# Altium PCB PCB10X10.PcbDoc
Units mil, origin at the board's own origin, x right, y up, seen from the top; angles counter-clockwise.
Board outline 3937.01 x 3937.01 mil, 2 copper layers (Top Layer, Bottom Layer); 55 components, 39 nets, 181 pads, 21 vias.
Unrouted connection lines stored in the file: 1.
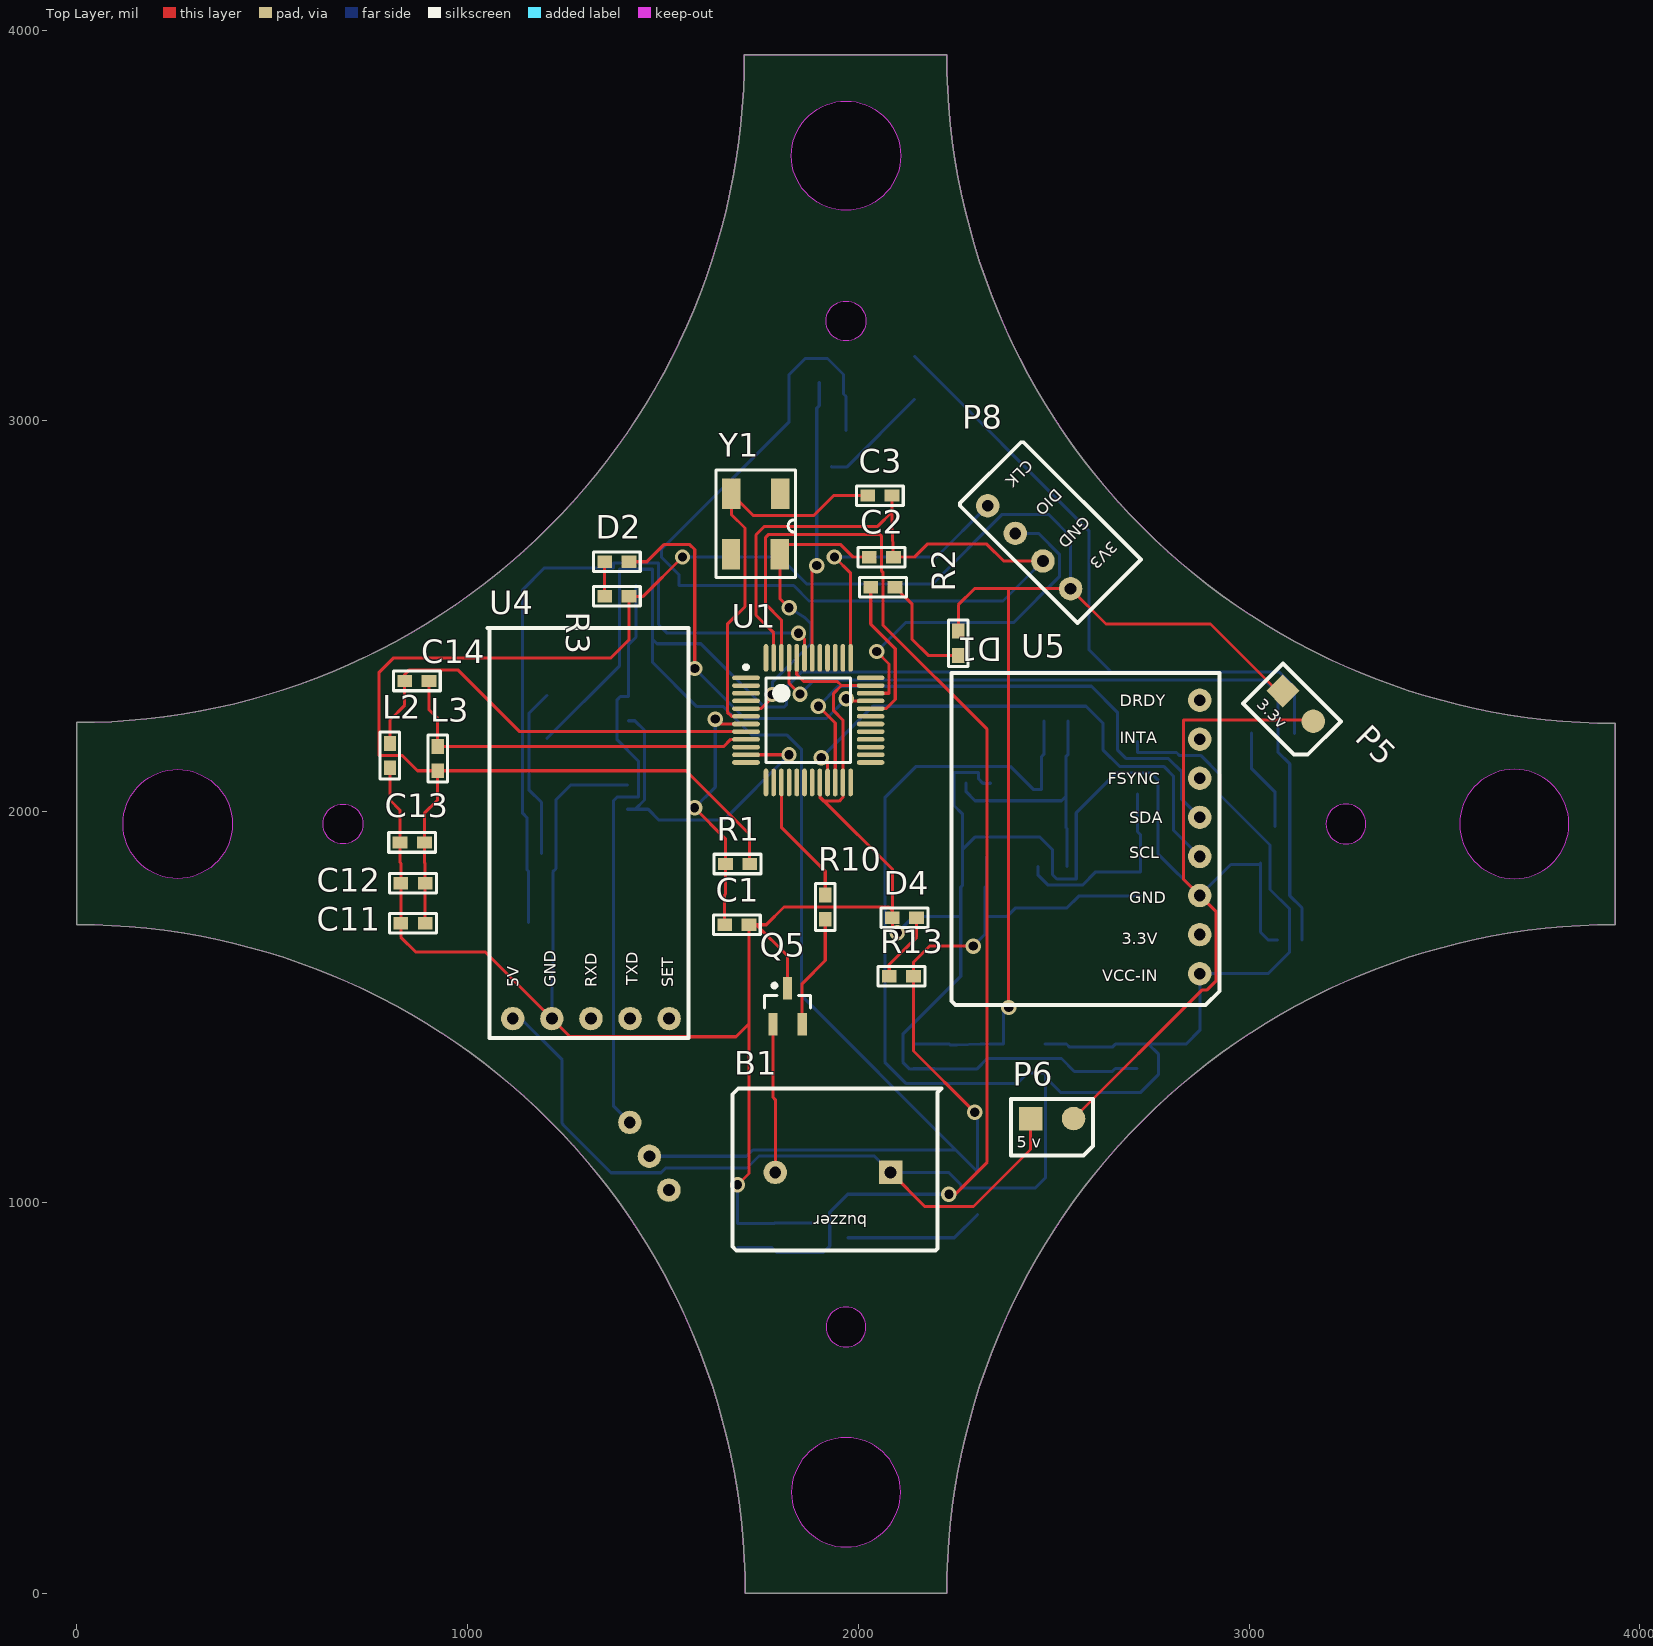
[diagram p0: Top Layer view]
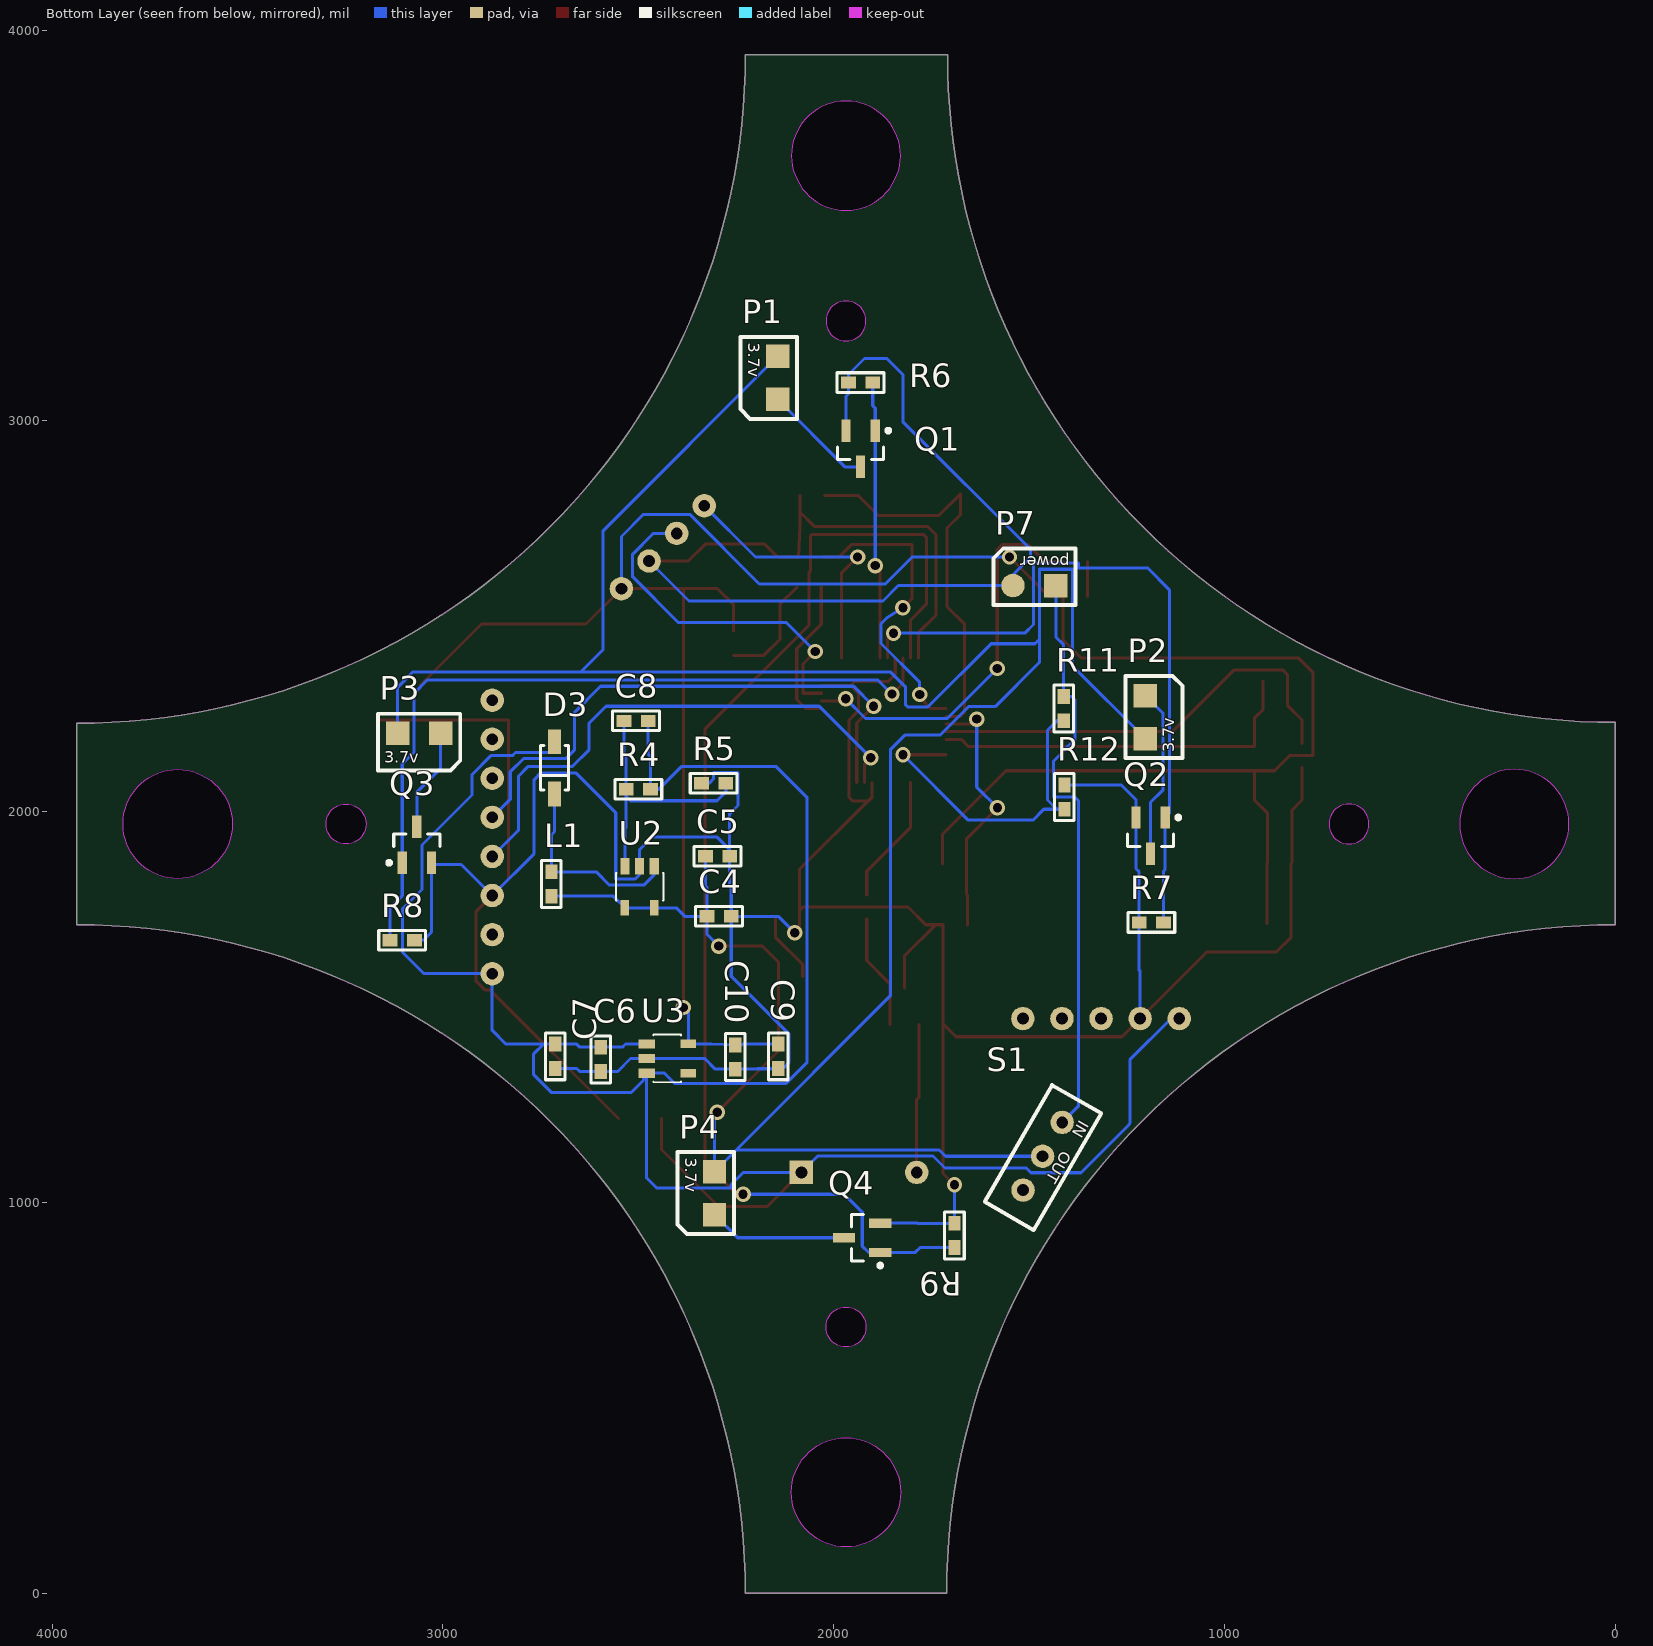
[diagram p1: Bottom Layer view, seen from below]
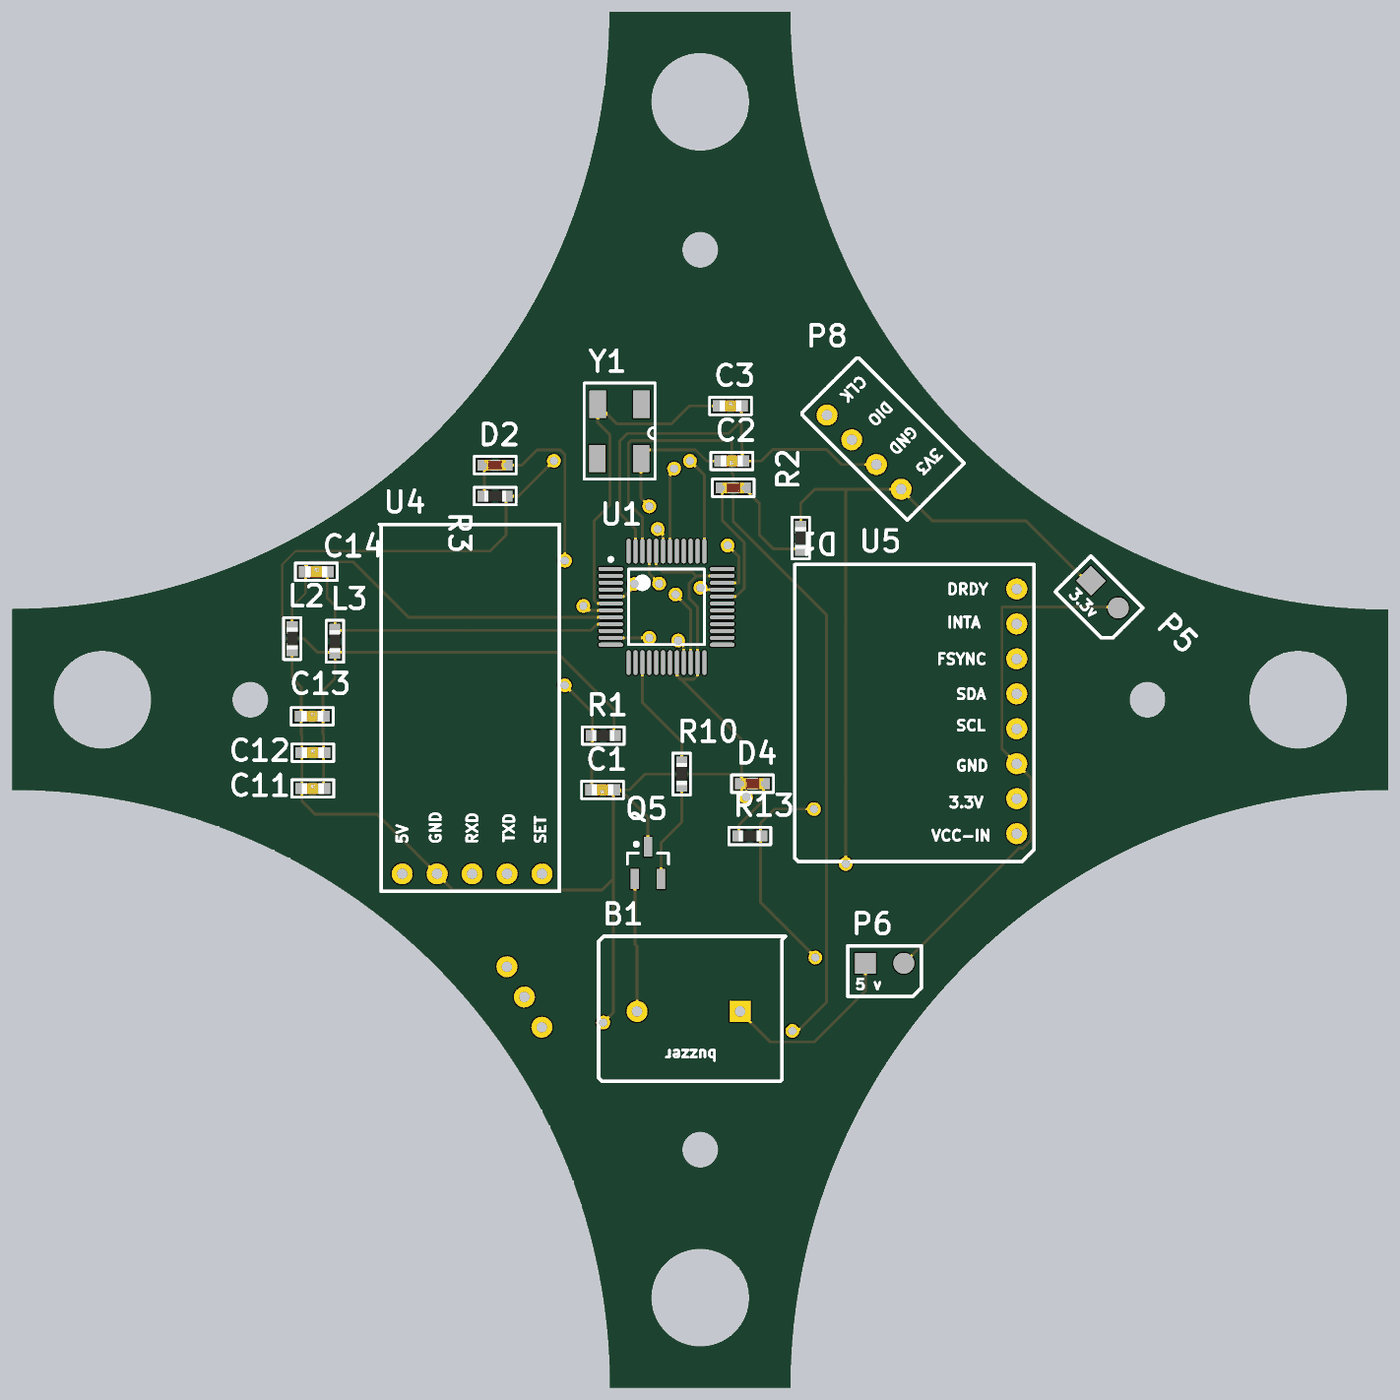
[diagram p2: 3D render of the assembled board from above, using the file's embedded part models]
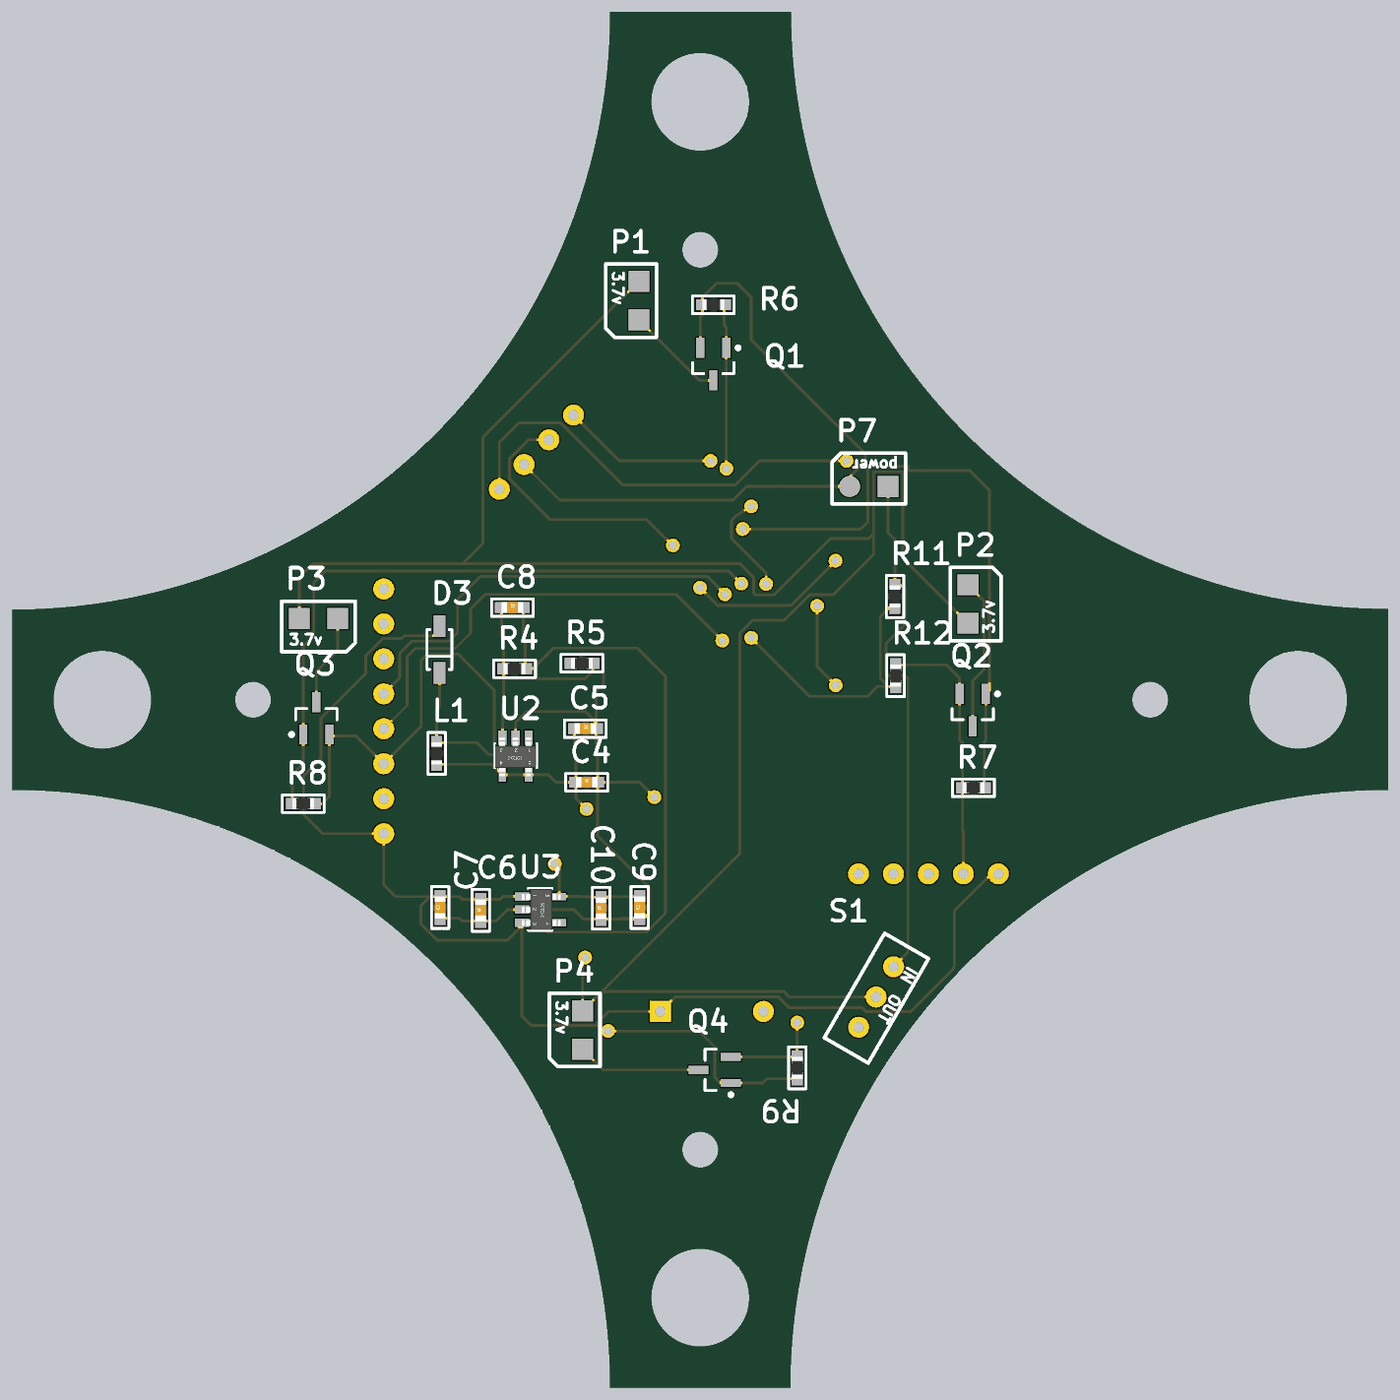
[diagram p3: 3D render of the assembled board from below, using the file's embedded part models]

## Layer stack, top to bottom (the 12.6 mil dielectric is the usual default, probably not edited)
Top Solder: solder mask 0.4, Solder Resist, Dk 3.5
Top Layer: signal copper 1.4
Dielectric 1: dielectric 12.6, FR-4, Dk 4.8
Bottom Layer: signal copper 1.4
Bottom Solder: solder mask 0.4, Solder Resist, Dk 3.5

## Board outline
0,1710.63 0,2228.33 ccw(c0,3937.01) 1708.68,3937.01 2226.38,3937.01 ccw(c3937.01,3937.01) 3937.01,2226.38 3937.01,1710.63 ccw(c3937.01,0) 2226.38,0 1710.63,0 ccw(c0,0)
cut-out: 1968.5,3539.36 cw(c1968.5,3679.13) 1828.73,3679.13 cw(c1968.5,3679.13) 1968.5,3818.91 cw(c1968.5,3679.13) 2108.28,3679.13 cw(c1968.5,3679.13)
cut-out: 3539.36,1968.5 ccw(c3679.13,1968.5) 3679.13,1828.73 ccw(c3679.13,1968.5) 3818.91,1968.5 ccw(c3679.13,1968.5) 3679.13,2108.28 ccw(c3679.13,1968.5)
cut-out: 1828.73,257.87 ccw(c1968.5,257.87) 1968.5,118.1 ccw(c1968.5,257.87) 2108.28,257.87 ccw(c1968.5,257.87) 1968.5,397.65 ccw(c1968.5,257.87)
cut-out: 257.87,1828.73 cw(c257.87,1968.5) 118.1,1968.5 cw(c257.87,1968.5) 257.87,2108.28 cw(c257.87,1968.5) 397.65,1968.5 cw(c257.87,1968.5)
cut-out: 681.1,1917.32 cw(c681.1,1968.5) 629.92,1968.5 cw(c681.1,1968.5) 681.1,2019.68 cw(c681.1,1968.5) 732.28,1968.5 cw(c681.1,1968.5)
cut-out: 3196.85,1968.5 ccw(c3248.03,1968.5) 3248.03,1917.32 ccw(c3248.03,1968.5) 3299.21,1968.5 ccw(c3248.03,1968.5) 3248.03,2019.68 ccw(c3248.03,1968.5)
cut-out: 1917.32,681.1 ccw(c1968.5,681.1) 1968.5,629.92 ccw(c1968.5,681.1) 2019.68,681.1 ccw(c1968.5,681.1) 1968.5,732.28 ccw(c1968.5,681.1)
cut-out: 1968.5,3204.72 cw(c1968.5,3255.91) 1917.32,3255.91 cw(c1968.5,3255.91) 1968.5,3307.09 cw(c1968.5,3255.91) 2019.68,3255.91 cw(c1968.5,3255.91)

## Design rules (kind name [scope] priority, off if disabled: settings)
Clearance [All] p1: gap=7.87
DiffPairsRouting [All] p1: maxlimit=7.87 minlimit=7.87 mostfreqgap=7.87 toplayer_minwidth=15 toplayer_maxwidth=15 toplayer_prefwidth=15 bottomlayer_minwidth=15 bottomlayer_maxwidth=15 bottomlayer_prefwidth=15 maxuncoupledlength=500
PolygonConnect [All] p1: connectstyle=Relief reliefconductorwidth=10 reliefentries=4 polygonreliefangle="90 Angle" airgapwidth=10
RoutingCorners [All] p1: cornerstyle=45-Degree minsetback=78.74 maxsetback=78.74
RoutingVias [All] p1: holewidth=23.62 width=39.37 viastyle="Through Hole" minholewidth=28 minwidth=50 maxholewidth=31.5 maxwidth=59.06
SolderMaskExpansion [All] p1: expansion=4
Width [All] p1: maxlimit=19.68 minlimit=7.87 preferedwidth=7.87
28 further rules are at their usual default settings.

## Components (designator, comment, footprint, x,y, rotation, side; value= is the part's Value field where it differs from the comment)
B1 "Buzzer" Buzzer 2082.68,1076.77 r180 top
C1 "Cap" 0603-N-CAP 1688.98,1710.63 r180 top
C2 "Cap" 0603-N-CAP 2059.06,2651.57 r180 top
C3 "Cap" 0603-N-CAP 2055.12,2809.06 r0 top
C4 "Cap" 0603-N-CAP 2293.31,1732.28 r180 bottom
C5 "Cap" 0603-N-CAP 2297.24,1885.83 r180 bottom
C6 "Cap" 0603-N-CAP 2596.46,1366.14 r90 bottom
C7 "Cap" 0603-N-CAP 2712.6,1374.02 r90 bottom
C8 "Cap" 0603-N-CAP 2505.91,2232.28 r180 bottom
C9 "Cap" 0603-N-CAP 2141.73,1374.02 r90 bottom
C10 "Cap" 0603-N-CAP 2251.97,1372.05 r90 bottom
C11 "Cap" 0603-N-CAP 860.24,1714.57 r0 top
C12 "Cap" 0603-N-CAP 860.24,1816.93 r0 top
C13 "Cap" 0603-N-CAP 858.27,1921.26 r0 top
C14 "Cap" 0603-N-CAP 870.08,2334.65 r0 top
D1 "D2" "0603-N - LED-RED" 2062.99,2574.8 r180 top
D2 "D2" "0603-N - LED-RED" 1381.89,2639.76 r0 top
D3 "MBR0520" 425 2714.57,2112.2 r90 bottom
D4 "D2" "0603-N - LED-RED" 2118.11,1728.35 r180 top
L1 "Inductor" "0603-N - res" 2722.44,1814.96 r90 bottom
L2 "Inductor" "0603-N - res" 801.18,2143.7 r90 top
L3 "Inductor" "0603-N - res" 923.23,2135.83 r90 top
P1 "motor1" Motor 2143.7,3165.35 r270 bottom
P2 "motor2" Motor 1202.76,2187.24 r90 bottom
P3 "motor3" Motor 3115.91,2200.79 r180 bottom
P4 "motor4" Motor 2305.12,1078.74 r270 bottom
P5 "3.3V_GND" 3.3V_GND 3086.61,2309.06 r315 top
P6 "5V_GND" 5V_GND 2440.94,1214.57 r0 top
P7 "Power_GND" Power_GND 1431.1,2578.74 r0 bottom
P8 "SW_download" SW_download 2543.31,2570.87 r135 top
Q1 "SI2302" SOT-23_M 1931.1,2929.13 r270 bottom
Q2 "SI2302" SOT-23_M 1188.98,1938.95 r270 bottom
Q3 "SI2302" SOT-23_M 3066.93,1915.35 r90 bottom
Q4 "SI2302" SOT-23_M 1927.17,909.45 r0 bottom
Q5 "NPN" SOT23_M 1818.9,1501.97 r90 top
R1 "Res2" "0603-N - res" 1690.94,1866.14 r180 top
R2 "Res1" "0603-N - res" 2255.91,2431.1 r90 top
R3 "Res1" "0603-N - res" 1381.89,2551.18 r0 top
R4 "Res1" "0603-N - res" 2500,2057.09 r180 bottom
R5 "Res1" "0603-N - res" 2307.09,2072.83 r180 bottom
R6 "Res1" "0603-N - res" 1931.1,3098.43 r180 bottom
R7 "Res1" "0603-N - res" 1187.01,1716.54 r180 bottom
R8 "Res1" "0603-N - res" 3104.33,1671.26 r0 bottom
R9 "Res1" "0603-N - res" 1690.94,915.35 r270 bottom
R10 "Res1" "0603-N - res" 1915.35,1755.91 r90 top
R11 "Res1" "0603-N - res" 1411.42,2263.78 r270 bottom
R12 "Res1" "0603-N - res" 1409.45,2037.4 r90 bottom
R13 "Res1" "0603-N - res" 2110.24,1578.74 r0 top
S1 "switch" SWITCH 1415.35,1204.72 r300 bottom
U1 "STM32F101C8T6" LQFP48_N 1872.05,2234.25 r0 top
U2 "LM27313" SOT-23_5-001 2459.46,1860.24 r0 bottom
U3 "MIC5205" SOT-23_5-001 2478.35,1405.51 r270 bottom
U4 "433" 433 1515.75,1470.47 r180 top
U5 "MPU6050_10" MPU6050_10 2874.02,2285.43 r270 top
Y1 "8M" 5032_ 1799.21,2834.65 r270 top

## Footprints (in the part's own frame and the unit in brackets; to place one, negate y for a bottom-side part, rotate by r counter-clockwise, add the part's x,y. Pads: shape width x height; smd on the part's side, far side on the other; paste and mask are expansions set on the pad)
3.3V_GND [mil]
  rect 60x60 smd: 1(0,0)
  round 60 smd: 2(110,0)
  silkscreen extent -50,-95 160,50
5V_GND [mil]
  rect 60x60 smd: 1(0,0)
  round 60 smd: 2(110,0)
  silkscreen extent -50,-95 160,50
425 [mm] "SOD-123; 2 Leads; Body 2.7 x 1.6 mm, (LxW)"
  rect 1.6x0.85 smd: 1(-1.7,0) 2(1.7,0)
  silkscreen extent -1.45,-0.9 1.45,0.9
433 [mil]
  round 60 hole 30: 1(0,0) 2(100,0) 3(200,0) 4(300,0) 5(400,0)
  silkscreen extent -50,-1000 465,50
"0603-N - LED-RED" [mm]
  rect 0.96x0.8 smd: 1(-0.79,0) 2(0.79,0)
  silkscreen extent -1.52,-0.64 1.52,0.63, body extent -0.8,-0.4 0.8,0.4, height 0.6
"0603-N - res" [mm]
  rect 0.96x0.8 smd: 1(-0.79,0) 2(0.79,0)
  silkscreen extent -1.52,-0.63 1.52,0.64, body extent -0.8,-0.4 0.8,0.4, height 0.4
0603-N-CAP [mm]
  rect 0.96x0.8 smd: 1(-0.79,0) 2(0.79,0)
  silkscreen extent -1.52,-0.63 1.52,0.64, body extent -0.8,-0.4 0.8,0.4, height 0.3
5032_ [mm]
  rect 2x1.2 smd: 1(0.533,-3.15) 2(4.47,-3.175) 3(4.47,0) 4(0.533,0.025)
  silkscreen extent -1.02,-4.14 5.97,1.02, body extent -0.03,-3.15 5,0.05, height 0.8
Buzzer [mil]
  rect 60x60 hole 30: 1(0,0)
  round 60 hole 30: 2(295,0)
  silkscreen extent -130,-215 405,200
LQFP48_N [mm] "Thin QFP, 48-Leads, Body 7x7mm, Pitch 0.5mm, IPC Medium Density"
  oval 1.8x0.3 smd: 1(-4.05,2.75) 2(-4.05,2.25) 3(-4.05,1.75) 4(-4.05,1.25) 5(-4.05,0.75) 6(-4.05,0.25) 7(-4.05,-0.25) 8(-4.05,-0.75) 9(-4.05,-1.25) 10(-4.05,-1.75) 11(-4.05,-2.25) 12(-4.05,-2.75) 25(4.05,-2.75) 26(4.05,-2.25) 27(4.05,-1.75) 28(4.05,-1.25) 29(4.05,-0.75) 30(4.05,-0.25) 31(4.05,0.25) 32(4.05,0.75) 33(4.05,1.25) 34(4.05,1.75) 35(4.05,2.25) 36(4.05,2.75)
  oval 0.3x1.8 smd: 13(-2.75,-4.05) 14(-2.25,-4.05) 15(-1.75,-4.05) 16(-1.25,-4.05) 17(-0.75,-4.05) 18(-0.25,-4.05) 19(0.25,-4.05) 20(0.75,-4.05) 21(1.25,-4.05) 22(1.75,-4.05) 23(2.25,-4.05) 24(2.75,-4.05) 37(2.75,4.05) 38(2.25,4.05) 39(1.75,4.05) 40(1.25,4.05) 41(0.75,4.05) 42(0.25,4.05) 43(-0.25,4.05) 44(-0.75,4.05) 45(-1.25,4.05) 46(-1.75,4.05) 47(-2.25,4.05) 48(-2.75,4.05)
  silkscreen extent -4.17,-2.75 2.75,3.57, body extent -3.5,-3.5 3.5,3.5, height 1.6
Motor [mil]
  rect 60x60 smd: 1(0,0) 2(110,0)
  silkscreen extent -50,-95 160,50
MPU6050_10 [mil] "mpu6050_10轴传感器"
  round 60 hole 30: 0(0,0) 1(100,0) 2(200,0) 3(300,0) 4(400,0) 5(500,0) 6(600,0) 7(700,0)
  silkscreen extent -70,-635 780,50
Power_GND [mil]
  rect 60x60 smd: 1(0,0)
  round 60 smd: 2(110,0)
  silkscreen extent -50,-95 160,50
SOT23_M [mm] "SOT23, 3-Leads, Body 2.9x1.3mm, Pitch 0.95mm, Lead Span 2.3mm - Reverse Pinning, IPC Low Density"
  rect 1.45x0.6 smd: 1(1.175,0) 2(-1.175,-0.95) 3(-1.175,0.95)
  silkscreen extent -0.1,-1.5 1.47,1.5, body extent -0.7,-1.5 0.7,1.5, height 1.1
SOT-23_5-001 [mm]
  rect 0.6x1.05 smd: 1(0,0) 2(0.95,0) 3(1.9,0)
  rect 0.55x1 smd: 4(1.9,2.7) 5(0,2.7)
  silkscreen extent -0.61,0.42 2.49,2.22, body extent -0.49,0 2.41,2.8, height 1.09
SOT-23_M [mm] "SOT23, 3-Leads, Body 2.9x1.3mm, Pitch 0.95mm, Lead Span 2.3mm, IPC Low Density"
  rect 1.45x0.6 smd: 1(-1.175,0.95) 2(-1.175,-0.95) 3(1.175,0)
  silkscreen extent -1.3,-1.5 0.7,1.92, body extent -0.7,-1.5 0.7,1.5, height 1.11
SW_download [mil]
  round 60 hole 30: 1(0,0) 2(100,0) 3(200,0) 4(300,0)
  silkscreen extent -75,-180 355,50
SWITCH [mil]
  round 60 hole 30: 1(0,0) 2(100,0) 3(200,0)
  silkscreen extent -70,-70 275,75

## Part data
C1 C2 C3 C4 C5 C6 C7 C8 C9 C10 C11 C12 C13 C14: "Capacitor"
D1 D2 D4: library part LED3, "Typical BLUE SiC LED"
D3: library part Diode, "Default Diode"
P1 P2 P3 P4: library part motor, "电机连接口"
Q1 Q2 Q3 Q4: library part IRLML2402, "HEXFET Power MOSFET"
Q5: library part 2N3904, "NPN General Purpose Amplifier"
R1 R2 R3 R4 R5 R6 R7 R8 R9 R10 R11 R12 R13: "Resistor"
U1: "STM32 ARM-based 32-bit MCU with 64 Kbytes Flash, 48-pin LQFP, Industrial Temperature"
U2: "3.7V升压到5v"
U3: "5V降压到3.3V"
U4: "通讯模块"
U5: library part MPU6050, "MPU6050_10轴"
Y1: library part XTAL, "Crystal Oscillator"

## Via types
v1: diameter 39.37, hole 23.62, Top Layer to Bottom Layer, 21 vias

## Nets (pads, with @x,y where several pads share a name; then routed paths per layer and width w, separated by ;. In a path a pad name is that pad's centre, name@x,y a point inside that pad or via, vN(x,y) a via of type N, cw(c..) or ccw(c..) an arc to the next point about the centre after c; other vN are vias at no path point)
3.3V: C9.2 C10.2 C11.2 C12.2 C13.2 L3.1 P5.1 P8.1 R1.1 R2.2 R3.2 U3.5 | length 6335.1
  Top Layer w7.87: C11.2 C12.2 891.34,1867.91 889.37,1869.88 C13.2 889.37,1995.91 923.23,2029.77 L3.1 ; v1(1549.91,2651.91) 1449.18,2551.18 R3.2 1412.99,2439.99 1366.91,2393.91 810.91,2393.91 772.91,2355.91 772.91,2143.91 832.73,2143.91 871.91,2104.73 L3.1 ; R1.1 1722.05,1941.64 1558.97,2104.73 L3.1 ; R2.2 2255.91,2529.53 2297.24,2570.87 2384.91,2570.87 ; v1(2384.91,1498.91) 2384.91,2570.87 ; P5.1@3059.06,2322.83 2901.57,2480.32 2633.86,2480.32 P8.1 2384.91,2570.87
  Bottom Layer w7.87: v1(1549.91,2651.91) 1798.91,2651.91 1867.91,2582.91 2190.22,2582.91 2368.22,2760.91 2486.91,2760.91 2543.31,2704.52 P8.1 ; C9.2 2232.83,1405.12 2234.8,1403.15 C10.2 2312.28,1405.51 U3.5@2371.91,1405.51 ; U3.5 U3.5@2371.91,1405.51 ; v1(2384.91,1498.91) 2371.91,1485.91 U3.5@2371.91,1405.51
3.7V: P7.1 R11.1 S1.1 | length 1503.4
  Bottom Layer w7.87: S1.1 1373.91,1246.17 1373.91,2028.79 1382.91,2037.79 1437.01,2037.79 1437.01,2129.91 1382.91,2184.01 1382.91,2286.88 1390.91,2294.88 R11.1 1411.42,2426.91 1431.1,2446.6 P7.1
3.7VOUT: C4.1 C5.1 L1.1 P1.1 P2.1 P3.1 P4.1 R13.2 S1.2 U2.4 U2.5 | length 7730
  Top Layer w7.87: v1(2293.91,1655.91) 2182.34,1655.91 2141.34,1614.91 R13.2 2141.34,1387.49 v1(2297.91,1230.91)
  Bottom Layer w7.87: P2.1 1389.29,2373.78 1389.29,2620.55 1472.92,2620.55 1472.92,2441.91 ; S1.2 1713.91,1118.12 1730.12,1134.33 2249.53,1134.33 ; P1.1 2589.91,2719.14 2589.91,2414.91 2646.91,2357.91 ; v1(2293.91,1655.91) 2324.41,1686.41 C4.1 ; v1(2297.91,1230.91) 2305.12,1223.71 P4.1 2249.53,1134.33 ; C5.1 2328.35,1810.85 2324.41,1806.91 C4.1 ; L1.1 2564.19,1783.86 U2.4 U2.5 2402.57,1753.94 2380.91,1732.28 C4.1 ; P3.1 3115.91,2318.91 3076.91,2357.91 2646.91,2357.91 ; 1472.92,2441.91 1484.91,2429.91 1596.91,2429.91 1758.41,2268.42 1810.91,2268.42 1815.91,2273.42 1815.91,2318.91 1854.91,2357.91 2646.91,2357.91 ; 1472.92,2441.91 1472.92,2382.91 1586.92,2268.91 1654.91,2268.91 1727.91,2195.91 1817.91,2195.91 1854.91,2158.91 1854.91,1528.94 2249.53,1134.33
5V: B1.1 C6.2 C7.2 C8.2 D3.2 P6.1 R4.2 U3.1 U3.3 U4.5 U5.7 | length 6282.4
  Top Layer w7.87: B1.1 2170.03,989.42 2294.91,989.42 2440.95,1135.45 P6.1
  Bottom Layer w7.87: U4.5 1136.35,1470.47 1241.91,1364.91 1241.91,1202.97 1244.09,1200.79 1244.09,1198.73 1366.91,1075.91 1494.91,1075.91 1506.91,1087.91 1715.24,1087.91 1745.91,1118.58 2040.87,1118.58 B1.1 2231.06,1076.77 2262.91,1044.91 2262.91,1036.91 2452.91,1036.91 2478.91,1062.91 U3.3@2478.91,1330.71 ; C8.2 2474.8,2146.82 2468.9,2140.91 R4.2 2447.74,2057.09 2388.68,2116.14 2148.14,2116.14 2067.93,2035.93 2067.93,1358.89 2122.91,1303.91 2406.12,1303.91 2432.91,1330.71 U3.3 U3.3@2478.91,1330.71 ; U3.1 2532.91,1405.51 2541.18,1397.24 C6.2 2649.91,1397.24 2657.79,1405.12 C7.2 2742.91,1405.12 ; D3.2 2714.57,2151.57 2814.55,2151.57 2822.68,2143.45 2877.38,2143.45 2925.91,2094.91 2925.91,2042.91 3053.91,1914.91 3053.91,1800.94 3103.94,1750.91 3103.94,1640.94 3048.43,1585.43 U5.7 2874.02,1440.22 2838.91,1405.12 2742.91,1405.12 ; U3.3@2478.91,1330.71 2486.91,1330.71 2486.91,1312.91 2518.91,1280.91 2721.91,1280.91 2767.91,1326.91 2767.91,1380.12 2742.91,1405.12
BUZZER: R10.2 U1.15 | length 334.3
  Top Layer w7.87: U1.15 1803.15,1959.91 1915.35,1847.71 R10.2
GND: C1.1 C2.1 C3.2 C4.2 C5.2 C6.1 C7.1 C9.1 C10.1 C11.1 C12.1 C13.1 D4.2 L2.1 P5.2 P6.2 P7.2 P8.2 Q1.2 Q2.2 Q3.2 Q4.2 Q5.1 R5.1 R6.1 R7.1 R8.1 R9.1 R12.2 U1.20 U1.23 U1.35 U1.44 U1.47 U2.2 U3.2 U4.4 U5.5 | length 13049.4
  Top Layer w7.87: L2.1 801.18,2029.9 827.17,2003.91 C13.1 827.17,1869.88 829.13,1867.91 C12.1 C11.1 829.13,1678.91 867.13,1640.91 1045.31,1640.91 U4.4 1262.31,1423.91 1686.91,1423.91 1720.08,1457.08 ; v1(1690.95,1044.95) 1720.08,1074.08 1720.08,1457.08 ; U1.47 1783.47,2457.66 1738.19,2502.94 1738.19,2708.66 1759.84,2730.32 2049.62,2730.32 2086.22,2766.91 ; Q5.1 1818.9,1630.91 1739.18,1710.63 ; U1.44 1842.52,2350.91 1860.01,2333.43 1946.34,2333.43 1956.93,2322.84 ; U1.20 1901.58,2038.58 ; U1.35 1956.93,2322.84 ; C3.2 2086.22,2766.91 ; v1(2099.91,1689.91) 2087.01,1702.82 D4.2 2087.01,1747.82 ; P8.2 2372.25,2641.58 2328.91,2684.91 2176.25,2684.91 2142.91,2651.58 C2.1 2086.22,2731.85 2086.22,2766.91 ; P6.2 2880.29,1543.91 2892.91,1543.91 2915.91,1566.91 2915.91,1743.54 U5.5 2831.91,1827.54 2831.91,2234.25 P5.2@3161.42,2234.25 ; 1720.08,1457.08 C1.1 1739.18,1710.63 ; 1739.18,1710.63 1764.63,1710.63 1809.91,1755.91 2078.91,1755.91 2087.01,1747.82 ; 1901.58,2038.58 1913.24,2026.91 ; 1901.58,2038.58 1901.58,2036.25 1910.91,2026.91 1913.24,2026.91 ; 1913.24,2026.91 1950.91,2026.91 1960.63,2036.63 U1.23 1960.63,2234.4 1937.01,2258.02 1937.01,2302.91 1956.93,2322.84 ; 1913.24,2026.91 2087.01,1853.14 2087.01,1747.82
  Bottom Layer w7.87: U4.4 1215.75,1591.91 1218.11,1594.28 R7.1 1218.11,1845.91 1226.39,1854.19 Q2.2 1226.39,2030.91 1263.98,2068.5 R12.2 ; v1(1690.95,1044.95) R9.1 1784.91,946.46 1785.31,946.85 Q4.2 ; Q1.2 1968.5,3062.99 1962.21,3069.29 R6.1 1962.21,3118.91 1921.21,3159.91 1863.91,3159.91 1822.91,3118.91 1822.91,2997.91 1495.91,2670.91 1495.91,2651.91 1541.1,2606.72 P7.2 1834.39,2578.74 1873.76,2539.37 2370.39,2539.37 P8.2 ; v1(2099.91,1689.91) 2142.28,1732.28 C4.2 ; C9.1 2194.91,1342.91 2196.88,1340.95 ; R5.1 2318.91,2072.84 2307.91,2083.84 2307.91,2100.4 2244.91,2100.4 2244.91,2015.91 2266.14,1994.69 2266.14,1902.91 ; C7.1 2657.79,1342.91 2649.91,1335.04 C6.1 2552.98,1335.04 2519.91,1368.11 U3.2 2330.08,1368.11 2302.91,1340.95 C10.1 2196.88,1340.95 ; Q3.2 Q3.2@3029.53,1864.91 ; R8.1 3049.89,1671.26 3029.53,1691.62 Q3.2@3029.53,1864.91 ; 2196.88,1340.95 2131.88,1340.95 2113.91,1358.91 2113.91,1430.62 2262.21,1578.91 C4.2 ; C4.2 2262.21,1806.91 2266.14,1810.85 C5.2 2266.14,1902.91 ; 2266.14,1902.91 2298.14,1934.91 2464.87,1934.91 2496.87,1902.91 U2.2 2496.87,1838.91 2508.03,1827.75 2557.91,1827.75 2557.91,1996.91 2660.42,2099.42 2749.41,2099.42 2766.78,2082.05 2766.78,1892.67 U5.5 2953.5,1864.91 Q3.2@3029.53,1864.91
IIC2_SCL: U1.21 U5.4 | length 1373.3
  Top Layer w7.87: v1(1905.26,2137.91) 1921.26,2121.91 U1.21
  Bottom Layer w7.87: v1(1905.26,2137.91) 2037.26,2269.91 2582.91,2269.91 2625.91,2226.91 2625.91,2158.91 2669.66,2115.17 2782.66,2115.17 2806.91,2090.91 2806.91,1952.54 U5.4
IIC2_SDA: U1.22 U5.3 | length 1446.7
  Top Layer w7.87: v1(1897.93,2269.93) 1940.95,2226.91 U1.22
  Bottom Layer w7.87: v1(1897.93,2269.93) 1949.02,2321.02 2596.81,2321.02 2662.91,2254.91 2662.91,2158.83 2685.91,2135.83 2794,2135.83 2827.91,2101.91 2827.91,2031.54 U5.3
LED_GRE: D2.2 U1.33 | length 1022.4
  Top Layer w7.87: D2.2 1458.77,2639.76 1502.42,2683.41 1568.91,2683.41 1581.41,2670.91 v1(1581.41,2366.42) ; v1(1968.91,2288.91) 1974.36,2283.47 U1.33
  Bottom Layer w7.87: v1(1581.41,2366.42) 1709.39,2238.43 1918.43,2238.43 v1(1968.91,2288.91)
LED_RED: D1.2 U1.32 | length 386.1
  Top Layer w7.87: U1.32 2070.91,2263.78 2094.49,2287.36 2094.49,2417.34 2031.89,2479.94 D1.2
NetB1_2: B1.2 Q5.3 | length 381.5
  Top Layer w7.87: Q5.3 1781.5,1269.1 1787.68,1262.91 B1.2
NetC1_2: C1.2 R1.2 U1.7 | length 665.6
  Top Layer w7.87: v1(1580.91,2009.91) 1659.84,1930.98 R1.2 1659.84,1788.88 1657.87,1786.91 C1.2 ; v1(1633.91,2236.91) 1646.42,2224.41 U1.7
  Bottom Layer w7.87: v1(1580.91,2009.91) 1633.91,2062.91 v1(1633.91,2236.91)
NetC2_2: C2.2 U1.5 Y1.3 | length 791.5
  Top Layer w7.87: U1.5 1750.91,2263.78 1779.91,2292.78 v1(1779.91,2299.91) ; v1(1822.91,2521.91) 1799.21,2545.61 Y1.3 1799.21,2683.41 1954.98,2683.41 1986.82,2651.58 C2.2
  Bottom Layer w7.87: v1(1779.91,2299.91) 1779.91,2331.39 1878.91,2430.39 1878.91,2480.91 1862.91,2496.91 v1(1822.91,2521.91)
NetC3_1: C3.1 U1.6 Y1.1 | length 1037
  Top Layer w7.87: U1.6 1675.73,2244.1 1664.91,2254.91 1664.91,2479.91 1709.91,2524.91 1709.91,2725.91 1675.21,2760.61 Y1.1 1730.95,2757.91 1885.91,2757.91 1937.06,2809.06 C3.1
NetC8_1: C8.1 R4.1 R5.2 U2.3 | length 666.8
  Bottom Layer w7.87: R5.2 2275.98,2050.84 2298.73,2028.1 2520.29,2028.1 2531.1,2038.91 ; U2.3 2534.27,1956.91 2531.1,1960.08 2531.1,2038.91 ; C8.1 2537.01,2146.82 2531.1,2140.91 R4.1 2531.1,2038.91
NetD1_1: D1.1 R2.1 | length 287
  Top Layer w7.87: D1.1 2137.8,2531.1 2137.8,2440.94 2178.74,2400 R2.1
NetD2_1: D2.1 R3.1 | length 88.6
  Top Layer w7.87: R3.1 D2.1
NetD3_1: D3.1 L1.2 U2.1 | length 512.3
  Bottom Layer w7.87: U2.1 2459.47,1838.36 2485.82,1812.01 2573.64,1812.01 2607.7,1846.06 L1.2 2722.44,1940.91 2714.57,1948.79 D3.1
NetD4_1: D4.1 R13.1 | length 178.6
  Top Layer w7.87: R13.1 2079.13,1608.83 2149.21,1678.91 D4.1
NetP1_2: P1.2 Q1.3 | length 285.4
  Bottom Layer w7.87: Q1.3 1931.1,2881.91 1970.26,2881.91 P1.2
NetP2_2: P2.2 Q2.3 | length 436.8
  Bottom Layer w7.87: Q2.3 1188.99,2023.84 1156.91,2055.91 1156.91,2251.4 P2.2
NetP3_2: P3.2 Q3.3 | length 264.5
  Bottom Layer w7.87: P3.2 3005.91,2110.94 3066.93,2049.91 Q3.3
NetP4_2: P4.2 Q4.3 | length 356.3
  Bottom Layer w7.87: Q4.3 2245.83,909.45 P4.2
NetQ5_2: Q5.2 R10.1 | length 293.6
  Top Layer w7.87: Q5.2 1856.3,1559.91 1915.35,1618.97 R10.1
PWR: R11.2 R12.1 U1.11 | length 867.1
  Top Layer w7.87: U1.11 v1(1822.67,2145.67)
  Bottom Layer w7.87: R12.1 1429.3,2006.3 ; R11.2 1428.15,2232.68 1452.76,2208.07 1452.76,2029.76 1429.3,2006.3 ; v1(1822.67,2145.67) 1655.42,1978.42 1490.11,1978.42 1462.23,2006.3 1429.3,2006.3
RX2_433: U1.13
RX2_434: U4.2
SET_433: U1.14
SET_434: U4.1
SWCLK: P8.4 U1.37 | length 721.9
  Top Layer w7.87: v1(1938.91,2651.91) 1980.32,2610.51 U1.37
  Bottom Layer w7.87: v1(1938.91,2651.91) 2200.09,2651.91 P8.4
SWDIO: P8.3 U1.34 | length 906.3
  Top Layer w7.87: U1.34 2078.74,2303.15 2078.74,2378.09 v1(2046.91,2409.91)
  Bottom Layer w7.87: v1(2046.91,2409.91) 2120.91,2483.91 2397.22,2483.91 2514.41,2601.1 2514.41,2658.9 2461.02,2712.29 P8.3
T4PWM1: Q1.1 R6.2 U1.42 | length 712.2
  Top Layer w7.87: U1.42 1881.89,2618.1 v1(1893.7,2629.91)
  Bottom Layer w7.87: v1(1893.7,2629.91) Q1.1 1893.7,3032.91 1900,3039.21 R6.2
T4PWM2: Q2.1 R7.2 U1.43 | length 1835
  Top Layer w7.87: v1(1846.91,2456.91) 1862.21,2441.62 U1.43
  Bottom Layer w7.87: R7.2 1155.91,1847.91 1151.58,1852.24 Q2.1 1140.91,1995.88 1140.91,2567.91 1196.98,2623.98 1373.54,2623.98 1373.54,2636.3 1488.66,2636.3 1488.66,2479.16 1510.91,2456.91 v1(1846.91,2456.91)
T4PWM3: Q3.1 R8.2 U1.45 | length 2013.5
  Top Layer w7.87: U1.45 1822.84,2328.99 v1(1850.91,2300.91)
  Bottom Layer w7.87: v1(1850.91,2300.91) 1886.91,2336.91 3039.91,2336.91 3073.91,2302.91 3073.91,2152.91 3104.33,2122.5 Q3.1 3104.33,1785.02 3135.43,1753.91 R8.2
T4PWM4: Q4.1 R9.2 U1.46 | length 3131.7
  Top Layer w7.87: U1.46 1803.15,2490.42 1762.91,2530.65 1762.91,2702.04 1770.79,2709.91 2054.91,2709.91 2058.91,2705.91 2058.91,2616.91 2062.91,2612.91 2062.91,2477.91 2329.91,2210.91 2329.91,1102.91 2247.91,1020.91 v1(2231.91,1020.91)
  Bottom Layer w7.87: R9.2 1778.91,884.25 1791.12,872.05 Q4.1 1910.91,872.05 1926.91,888.05 1926.91,974.91 1972.91,1020.91 v1(2231.91,1020.91)
TX2_433: U1.12
TX2_434: U4.3
VDDA: C14.2 L3.2 U1.9 | length 973.7
  Top Layer w7.87: C14.2 901.18,2260.96 923.23,2238.91 L3.2 1655.8,2166.93 1673.91,2185.04 U1.9
VSSA: C14.1 L2.2 U1.8 | length 1135.9
  Top Layer w7.87: L2.2 801.18,2234.91 838.98,2272.71 C14.1 838.98,2350.91 850.98,2362.91 974.91,2362.91 1133.1,2204.73 U1.8
pads on no net: S1.3 U1.1 U1.2 U1.3 U1.4 U1.10 U1.16 U1.17 U1.18 U1.19 U1.24 U1.25 U1.26 U1.27 U1.28 U1.29 U1.30 U1.31 U1.36 U1.38 U1.39 U1.40 U1.41 U1.48 U3.4 U5.0 U5.1 U5.2 U5.6 Y1.2 Y1.4

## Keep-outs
Keep-Out Layer:
  the board outline again, w1.97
